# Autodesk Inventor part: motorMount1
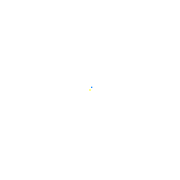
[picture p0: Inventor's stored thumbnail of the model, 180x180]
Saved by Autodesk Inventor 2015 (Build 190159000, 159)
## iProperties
Created: 2016-07
Part Number: motorMount1
Material: Generic
Document SubType Name: Modeling
Designer: user
Density: 1 g/cm^3
Appearance: Default
Author: user
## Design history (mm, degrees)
sketch "Sketch1"
  geometry: 1 further point
  constraints: 1 other
